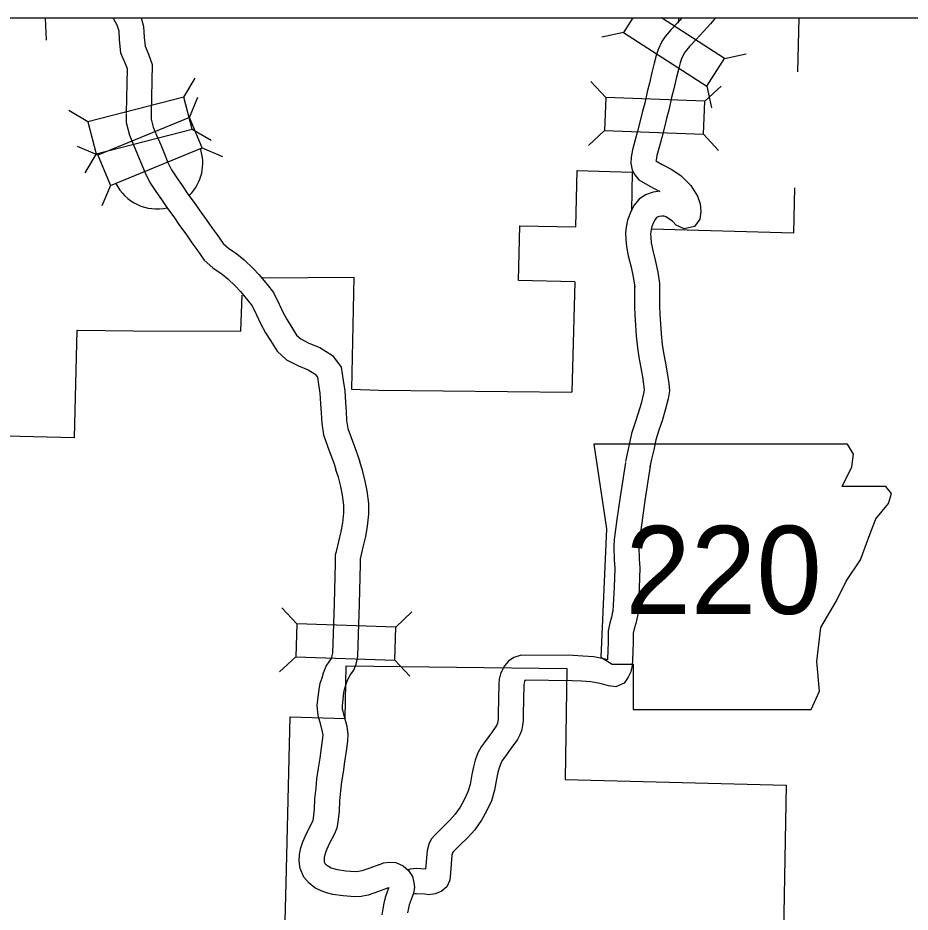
# Model space of a CAD drawing. Extents: x 535214 to 694517, y 381272 to 484355.
# Drawn here: x 542010 to 547357, y 474863 to 480223 of the extents above; entities that cross this region are included whole.
import ezdxf

# ---------------------------------------------------------------- set-up
doc = ezdxf.new("R2010")
doc.units = 0
for name, color, linetype in [('1', 7, 'Continuous'), ('Level 10', 7, 'Continuous'), ('Level 11', 7, 'Continuous'), ('Level 20', 7, 'Continuous'), ('Level 21', 7, 'Continuous'), ('Level 24', 7, 'Continuous'), ('Level 6', 7, 'Continuous'), ('Level 8', 7, 'Continuous')]:
    doc.layers.add(name, color=color, linetype=linetype)

msp = doc.modelspace()

# ---------------------------------------------------------------- linework, layer by layer
at = {"layer": '1'}
msp.add_lwpolyline([(535213.7, 480223.3), (566227, 480223.3), (566227, 448175.2), (535213.7, 448175.2)], close=True, dxfattribs=at)
at = {"layer": 'Level 10'}
for points in [[(542576.1, 480223.3), (542582.2, 480217.2), (542603.5, 480182), (542614, 480145.4), (542617.4, 480092.6), (542625.2, 480014.7), (542653.3, 479950.3), (542664.5, 479919)], [(542747.7, 480223.3), (542762.6, 480171.2), (542766.9, 480105), (542772.1, 480053), (542792.8, 480005.7), (542814.9, 479943.9)], [(542814.9, 479943.9), (542807.7, 479648.9)], [(542664.3, 479919), (542657.8, 479652.6)], [(542657.8, 479648.4), (542659.4, 479595.8), (542678.7, 479520.8), (542702.7, 479462.8), (542727.1, 479405), (542747.1, 479356.4), (542771.5, 479294.3), (542801, 479236.4), (542837.4, 479181.6), (542869.6, 479134.4), (542906.6, 479080.5), (542943.4, 479030.4), (542978.7, 478978.6), (543015.7, 478928), (543052.3, 478875.6), (543081.3, 478835), (543127.1, 478771), (543177.8, 478724.1), (543233.5, 478686.8), (543267.9, 478659.7), (543311.8, 478617.2), (543343, 478583.1), (543388.7, 478529.4), (543413.9, 478497.7), (543439.7, 478443.9), (543463.1, 478391.7), (543494.6, 478336.2), (543524.4, 478289.1), (543563.2, 478224.8), (543620.5, 478173.6), (543691.8, 478137), (543750.4, 478113.7), (543790.5, 478088.4), (543804.5, 478069.1), (543811.9, 478025.9), (543820.1, 477972.6), (543822.9, 477908.8), (543827.3, 477854.8), (543830.9, 477792.3), (543842, 477724.4), (543865.8, 477656.8), (543885.7, 477602.8), (543904.6, 477549.7), (543916, 477514.7)], [(542807.7, 479653.1), (542808.8, 479617.1), (542821.4, 479568.3), (542841.1, 479520.6), (542865.5, 479462.7), (542886.2, 479412.5), (542908.5, 479355.9), (542930.7, 479312.2), (542961.9, 479265.4), (542993.4, 479219), (543028.9, 479167.4), (543065.9, 479117), (543101.2, 479065.2), (543137.8, 479015.3), (543174.9, 478962.1), (543203.3, 478922.2), (543240.2, 478870.7), (543271.1, 478842.1), (543321.7, 478808.2), (543366.7, 478772.8), (543419.3, 478721.9), (543455.5, 478682.4), (543504.5, 478624.7), (543541.8, 478577.9), (543575.8, 478507), (543597.1, 478459.5), (543623.2, 478413.4), (543652, 478367.9), (543679.9, 478321.6), (543706, 478298.3), (543754, 478273.7), (543818.7, 478247.9), (543894.9, 478199.9), (543946.5, 478128.7), (543959.9, 478050), (543969.5, 477987.4), (543972.6, 477918.2), (543977, 477865.2), (543980.2, 477808.8), (543987.9, 477761.7), (544006.9, 477707.6), (544026.7, 477653.9), (544046.6, 477598.2), (544058.6, 477561.3)], [(544172.3, 475146.8), (544119.6, 475126.8), (544070.9, 475109.2), (544051.4, 475105.6), (544031.1, 475105.1), (543974.6, 475108.7), (543925.9, 475115.9), (543902.4, 475121.4), (543886.9, 475127.1), (543870.8, 475135.3), (543860.1, 475143.9), (543852.3, 475153), (543848.1, 475162.6), (543846.8, 475174.5), (543847.6, 475191), (543850.9, 475208.9), (543857.8, 475228.6), (543877.7, 475273.4), (543906.6, 475329.5), (543922.5, 475368), (543930.2, 475402.1), (543936.9, 475467.7), (543939.9, 475530.6), (543946.2, 475590.4), (543951.1, 475642.7), (543960.3, 475702.5), (543969.9, 475763), (543979.1, 475828.1), (543986.3, 475889.9), (543990, 475929.9), (543982.6, 475975), (543967.2, 476032.7), (543958.4, 476064.8), (543955.9, 476079.2), (543954.5, 476098.5), (543956.5, 476118.6), (543963.7, 476176.4), (543967.3, 476198), (543975.6, 476222.9), (543982.4, 476246.5), (543990.9, 476265.5), (544002.1, 476283.4), (544023.9, 476312.3), (544036.2, 476349.4), (544046.8, 476395.5), (544051.1, 476526.9), (544056.7, 476709.3), (544062.3, 476949.5), (544063.5, 476979.3), (544063.7, 476985.2), (544064.6, 476988.7), (544079.3, 477050.2), (544094.9, 477115.1), (544105.2, 477175.3), (544113.4, 477248.5), (544112.9, 477312.1), (544102.9, 477387.4), (544090.8, 477446), (544075.3, 477511.1), (544058.5, 477561.7)], [(544225.7, 475006.6), (544171.8, 474986.1), (544110.1, 474963.9), (544066.8, 474956), (544028.2, 474955), (543958.9, 474959.4), (543897.8, 474968.4), (543859.3, 474977.4), (543826.8, 474989.4), (543788.8, 475008.7), (543755.3, 475035.8), (543723.8, 475072.4), (543701.6, 475123.6), (543696.4, 475169.7), (543698.2, 475208.2), (543705.5, 475247.3), (543718.1, 475283.8), (543742.4, 475338.3), (543770.4, 475392.7), (543779, 475413.4), (543781.9, 475426.3), (543787.3, 475478.9), (543790.3, 475542.1), (543797, 475605.3), (543802.2, 475661.1), (543812.1, 475725.5), (543821.5, 475785.2), (543830.3, 475847.3), (543837.1, 475905.6), (543838.9, 475924.6), (543835.8, 475943.4), (543822.4, 475993.5), (543811.8, 476032.2), (543806.9, 476060.9), (543803.9, 476100.5), (543807.4, 476135.4), (543815.2, 476197.8), (543821.2, 476234.2), (543832.4, 476267.5), (543841.1, 476298), (543858.2, 476336.3), (543878.5, 476368.6), (543889.3, 476382.9), (543891.6, 476390), (543897.4, 476415), (543901.2, 476531.7), (543906.7, 476713.4), (543912.4, 476954.4), (543913.6, 476984.6), (543914.3, 477006.7), (543919.1, 477025.3), (543933.4, 477085), (543947.9, 477145.3), (543956.6, 477196.3), (543963.3, 477256.3), (543963, 477301.6), (543955, 477362.2), (543944.3, 477413.4), (543930.9, 477470.1), (543916.2, 477514.4)], [(544173, 475147.1), (544201, 475157.4), (544235.3, 475161.3), (544275.1, 475159.6), (544319.3, 475139.4), (544350.7, 475111.3), (544375, 475077.1), (544383.3, 475039.3), (544386.4, 475010.8), (544380.7, 474975.7), (544372.3, 474953.3), (544355, 474906.8), (544350.1, 474885.5), (544344.5, 474857.8)], [(544225, 475006.4), (544233.1, 475009.4), (544231.8, 475005.9), (544211, 474950), (544203.4, 474917.2), (544196.5, 474882.7), (544191.5, 474846)]]:
    msp.add_lwpolyline(points, dxfattribs=at)
at = {"layer": 'Level 11'}
msp.add_line((545855.1, 478630.7), (545856, 478619.5), dxfattribs=at)
for points in [[(545990, 480223.3), (545963.9, 480194.6), (545924.9, 480152.9), (545888.3, 480111.6), (545869.6, 480082.6), (545848, 480033), (545835.3, 479997.4), (545823.2, 479951.2), (545809.5, 479895.7), (545794.6, 479832.8), (545781.4, 479780.6), (545766.5, 479712.9), (545752.3, 479656.5), (545739.2, 479605.3), (545723.9, 479544.3), (545710, 479493.1), (545693.8, 479431.9), (545685, 479387.8), (545683.6, 479351.9), (545691.4, 479310.4), (545708.2, 479283.3), (545732, 479253.3), (545796.4, 479214.8), (545857.6, 479181.8)], [(546190.3, 480223.3), (546161.8, 480187.7), (546118.1, 480141.2), (546074.1, 480092.9), (546035.9, 480051.9), (546008.2, 480020.7), (546002.3, 480011.5), (545987.6, 479977.8), (545978.8, 479953.2), (545968.6, 479914.2), (545955.3, 479860.4), (545940.3, 479797.1), (545927.4, 479746), (545912.5, 479678.4), (545897.7, 479619.6), (545884.6, 479568.5), (545869, 479506.3), (545854.8, 479454.2), (545840, 479398.1), (545834.4, 479370.1), (545834.3, 479366.9), (545870.5, 479345.2), (545928.8, 479313.8), (545986, 479275.7), (546043.1, 479218.7), (546083.4, 479154.2), (546099.7, 479108.2), (546103.4, 479061.8), (546096.5, 479017.3), (546064.8, 478972), (546002.8, 478958.4), (545954.4, 478979.7), (545934, 479004), (545893.3, 479029.7), (545882.5, 479033.7), (545869.7, 479034.8), (545852.5, 479032.6), (545840.8, 479028.4), (545837, 479025.8), (545828.4, 479015.1), (545818.4, 478995.9), (545809.5, 478971.7), (545804.2, 478943.5), (545801.7, 478926.9), (545802.5, 478905.9), (545806.2, 478874.2), (545814.7, 478828.2), (545831, 478763.7), (545844.7, 478698.8), (545855.1, 478630.7)], [(545857.2, 479184.4), (545817.2, 479179.3), (545772.1, 479163.1), (545734.2, 479137.3), (545702.3, 479097.7), (545680.9, 479056.7), (545664.4, 479011.6), (545656.3, 478968.6), (545651.2, 478935.2), (545652.9, 478894.2), (545657.8, 478851.9), (545668.1, 478796.1), (545684.9, 478729.8), (545697.1, 478671.9), (545706.8, 478608.1)], [(545706, 478619.4), (545706, 478552.4), (545706, 478491.9), (545708, 478441), (545711, 478380.8), (545715.7, 478316.6), (545722.5, 478245.6), (545731.9, 478189.8), (545743.1, 478126.2), (545753.4, 478071.1), (545762.4, 478012.1), (545764.3, 477993.7), (545760, 477970.6), (545745.1, 477911), (545728, 477854.2), (545709.2, 477798.7), (545687.8, 477732.1), (545674.2, 477666.1), (545661.7, 477609.8), (545651.6, 477563.1)], [(545856, 478619.5), (545856, 478552.4), (545856, 478494.8), (545857.8, 478447.7), (545860.7, 478390), (545865.1, 478329.2), (545871.3, 478265.3), (545879.8, 478215.2), (545890.7, 478152.9), (545901.3, 478096.2), (545911.2, 478031.3), (545915.8, 477987.7), (545906.7, 477938.7), (545889.7, 477871.1), (545870.9, 477808.5), (545851.7, 477751.7), (545833.1, 477693.9), (545820.9, 477634.7), (545808.3, 477577.7), (545798.2, 477531.3)], [(545650.8, 477558.5), (545619.2, 477351.9), (545600.2, 477216.5), (545583.7, 477095.5), (545582.2, 477054.9), (545584.4, 476973.7), (545586.7, 476925.5), (545582.8, 476810), (545579.5, 476738.3), (545575.4, 476667.4), (545572.5, 476653.6), (545567.2, 476630.9), (545557.2, 476595.6), (545547.9, 476548.5), (545548.2, 476517), (545547, 476481.7), (545544.4, 476381.9), (545544, 476375.8), (545530.3, 476379.3), (545462.3, 476392), (545396.5, 476396.8), (545337.2, 476400), (545026.1, 476403.1), (544982.7, 476389.1), (544950.1, 476368), (544926.1, 476339.6), (544911.5, 476313.9), (544901.9, 476290.7), (544894.8, 476259.6), (544893, 476231.1), (544888.5, 476050.9), (544887.8, 476019.5), (544886.3, 476005.8), (544883.9, 475995.5), (544879.4, 475984.6), (544874.6, 475974.9), (544847.7, 475937.7), (544805.2, 475877.3), (544787.3, 475853.4), (544767.2, 475818.4), (544750.7, 475773.8), (544739.9, 475734.5), (544730.5, 475687), (544720.7, 475627.4), (544707.3, 475584.3), (544684.6, 475536.5), (544660.3, 475492.7), (544630.8, 475449.3), (544597.7, 475413.4), (544553.9, 475370.1), (544510.3, 475326.8), (544487.1, 475299.1), (544473.4, 475270.2), (544462.5, 475231.7), (544453.1, 475119.7), (544396, 475123.7), (544359.9, 475119.5), (544349, 475116.3)], [(545799, 477535.8), (545767.6, 477330.1), (545748.8, 477196), (545733.3, 477082.7), (545732.3, 477054.3), (545734.3, 476979.3), (545736.8, 476926.6), (545732.7, 476803.9), (545729.3, 476730.5), (545724.5, 476647.2), (545718.9, 476620.9), (545712.5, 476593.5), (545703.2, 476560.6), (545698, 476534.5), (545698.2, 476515.1), (545697, 476477.3), (545694.2, 476375), (545692, 476341.3), (545684.1, 476303.1), (545667.1, 476270.1), (545642.8, 476236.1), (545593.4, 476213.9), (545548.9, 476218.6), (545520.7, 476226.9), (545497.9, 476232.7), (545443, 476243), (545387, 476247.1), (545332.5, 476250), (545049.3, 476252.8), (545046.6, 476248), (545045.4, 476245.1), (545043.8, 476238.1), (545042.9, 476224.5), (545038.4, 476047.5), (545037.6, 476009.9), (545034.5, 475980.5), (545027.2, 475949.6), (545016, 475922.4), (545003.2, 475896.9), (544969.9, 475850.6), (544926.6, 475789.2), (544912.9, 475770.8), (544903.5, 475754.5), (544893.6, 475727.9), (544886, 475700), (544878.1, 475660.3), (544867, 475592.8), (544847.4, 475529.5), (544818.1, 475467.8), (544788.2, 475414.1), (544748.7, 475355.8), (544705.6, 475309.1), (544659.4, 475263.5), (544620.8, 475225.1), (544614.4, 475217.5), (544614.3, 475217.3), (544610.7, 475204.7), (544601.8, 475097.7), (544597.9, 475053.4), (544580.4, 475014.2), (544546.2, 474985.4), (544509.7, 474971.3), (544473.7, 474967.1), (544448.7, 474969.7), (544399.6, 474973.1), (544389.9, 474972), (544382.9, 474969.9)]]:
    msp.add_lwpolyline(points, dxfattribs=at)
at = {"layer": 'Level 20'}
for p, q in [((542173.4, 480222.4), (542178.7, 480090.5)), ((545970.8, 480223.3), (545964.7, 480192)), ((545639.3, 480135.1), (545510.3, 480107.2)), ((546245.8, 479979.5), (546374.8, 480007.3)), ((543004.3, 479748.6), (543071.4, 479862.2)), ((545533.6, 479745.9), (545443.8, 479842.7)), ((546127.1, 479723.3), (546224, 479813)), ((546138.4, 479813.1), (546166.3, 479684.1)), ((543038, 479626.8), (543088.8, 479748.6)), ((542429, 479600.6), (542315.3, 479667.8)), ((543053.6, 479556.8), (543167.2, 479489.7)), ((545526, 479548), (545429.2, 479458.3)), ((546119.6, 479525.4), (546209.3, 479428.6)), ((542488.8, 479400.7), (542366.9, 479451.4)), ((542478.3, 479408.9), (542411.1, 479295.2)), ((543113.4, 479443.7), (543235.3, 479392.9)), ((542564.2, 479217.6), (542513.4, 479095.7)), ((543681, 476591), (543590.7, 476687.3)), ((544274.7, 476571.7), (544371, 476661.9)), ((543674.6, 476393.1), (543578.2, 476302.8)), ((544268.2, 476373.8), (544358.5, 476277.5))]:
    msp.add_line(p, q, dxfattribs=at)
for points in [[(542172.5, 480223.3), (542173.4, 480222.4), (542174.2, 480223.3)], [(545696.2, 480223.3), (545639.3, 480135.1), (546138.4, 479813.1), (546245.8, 479979.5), (545867.8, 480223.3)]]:
    msp.add_lwpolyline(points, dxfattribs=at)
for points in [[(542478.3, 479408.9), (543053.6, 479556.8), (543004.3, 479748.6), (542429, 479600.6)], [(545526, 479548), (546119.6, 479525.4), (546127.1, 479723.3), (545533.6, 479745.9)], [(542564.2, 479217.6), (543113.4, 479443.7), (543038, 479626.8), (542488.8, 479400.7)], [(543674.6, 476393.1), (544268.2, 476373.8), (544274.7, 476571.7), (543681, 476591)]]:
    msp.add_lwpolyline(points, close=True, dxfattribs=at)
at = {"layer": 'Level 21'}
msp.add_lwpolyline([(545461, 477668), (545537.1, 477160.5), (545503.3, 476390.7), (545570.9, 476348.4), (545697.8, 476348.4), (545697.8, 476077.7), (546763.6, 476077.7), (546814.4, 476187.7), (546797.5, 476365.3), (546822.8, 476568.3), (546915.9, 476729.1), (546975.1, 476847.5), (547059.7, 476974.4), (547110.5, 477109.7), (547152.7, 477219.7), (547228.9, 477312.7), (547245.8, 477371.9), (547212, 477414.2), (546949.7, 477414.2), (547008.9, 477532.7), (547017.4, 477608.8), (546982.3, 477667.3)], close=True, dxfattribs=at)
at = {"layer": 'Level 24'}
for start, end in [(315.5106, 18.908), (206.4652, 282.9592)]:
    msp.add_arc((542843, 479353), 275, start, end, dxfattribs=at)
at = {"layer": 'Level 6'}
for points in [[(543970.7, 476024), (543978.1, 476339.2), (545300.4, 476323.6), (545289.9, 475658.4)], [(543617.4, 475037), (543640.8, 476034.3), (543970.7, 476024)], [(545289.9, 475658.4), (546614.9, 475624.1)], [(546614.9, 475624.1), (546602.9, 474961.9)], [(543592.6, 474057.6), (543617.4, 475037)], [(546602.9, 474961.9), (546584.7, 473973.5), (547253.8, 473956.1)]]:
    msp.add_lwpolyline(points, dxfattribs=at)
at = {"layer": 'Level 8'}
for points in [[(546683.7, 479898.9), (546691.6, 480223.3)], [(545017.9, 478977.4), (545354.2, 478971.1), (545361.7, 479309)], [(545361.7, 479309), (545691.6, 479298.8)], [(545690.5, 479298.8), (545687.9, 479066.7)], [(546660, 478935.6), (546666.6, 479204.9)], [(545347.1, 478640.7), (545009.4, 478649.2), (545017.9, 478977.4)], [(545807.9, 478958.7), (546660, 478935.6)], [(543470.8, 478665.5), (544024, 478668.1)], [(544024, 478668.1), (544010.1, 477998.3)], [(545347.1, 478640.7), (545329.8, 477979.5)], [(542349.1, 477706.1), (542364, 478351.1), (542701.1, 478347.4), (543346.4, 478345.8), (543354.6, 478560.9)], [(542349.1, 477706.1), (541365.7, 477729.6), (541373.3, 478069.2)], [(544010.1, 477998.3), (544173.4, 477992.4)], [(544173.4, 477992.4), (545329.8, 477979.5)]]:
    msp.add_lwpolyline(points, dxfattribs=at)

# ---------------------------------------------------------------- texts
at = {"layer": 'Level 21'}
msp.add_text('220', height=528, dxfattribs=at).set_placement((545650.4, 476650.4))

doc.saveas('drawing.dxf')
